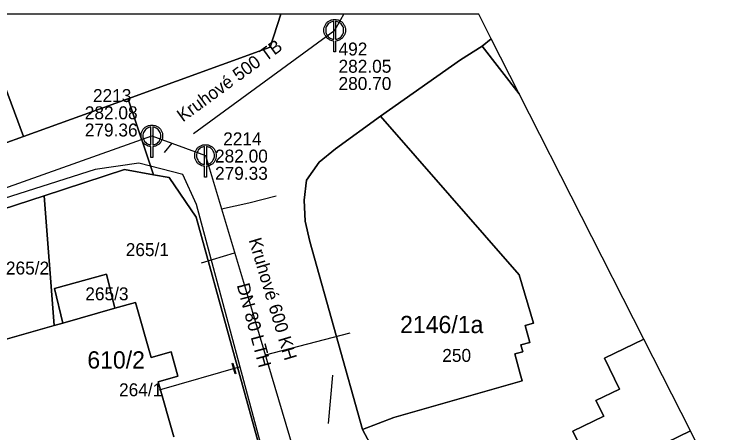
# Model space of a CAD drawing. Extents: x -571312 to -571060, y -1087128 to -1086933.
# Drawn here: x -571153.9 to -571071.4, y -1086981.5 to -1086932.9 of the extents above; entities that cross this region are included whole.
import ezdxf

# ---------------------------------------------------------------- set-up
doc = ezdxf.new("R2010")
doc.units = 0
for name, color, linetype in [('Adresní místo-text', 7, 'Continuous'), ('Armatura vodovodní', 7, 'Continuous'), ('Default', 7, 'Continuous'), ('Kanalizační přípojka', 7, 'Continuous'), ('Kanalizační stoka', 7, 'Continuous'), ('Kanalizační šachta', 7, 'Continuous'), ('Parcela-polygon', 7, 'Continuous'), ('Parcela-text', 7, 'Continuous'), ('Popis kmenové stoky', 7, 'Continuous'), ('Popis šachty', 7, 'Continuous'), ('Vodovodní přípojka', 7, 'Continuous'), ('Vodovodní řad', 7, 'Continuous'), ('Řad vodovodní popis', 7, 'Continuous')]:
    doc.layers.add(name, color=color, linetype=linetype)

msp = doc.modelspace()

# ---------------------------------------------------------------- linework, layer by layer
at = {"layer": 'Armatura vodovodní'}
msp.add_lwpolyline([(-571128.541, -1086973.395), (-571128.193, -1086974.595), (-571128.268, -1086974.617), (-571128.616, -1086973.417), (-571128.541, -1086973.395)], dxfattribs=at)
at = {"layer": 'Default'}
for points in [[(-571116.813, -1086935.988), (-571117.071, -1086935.97), (-571117.333, -1086935.824), (-571117.63, -1086935.66), (-571117.795, -1086935.363), (-571117.96, -1086935.065), (-571117.96, -1086934.74), (-571117.96, -1086934.413), (-571117.792, -1086934.113), (-571117.623, -1086933.812), (-571117.325, -1086933.651), (-571117.027, -1086933.49), (-571116.71, -1086933.49), (-571116.395, -1086933.49), (-571116.096, -1086933.651), (-571115.797, -1086933.812), (-571115.628, -1086934.113), (-571115.46, -1086934.413), (-571115.46, -1086934.74), (-571115.46, -1086935.065), (-571115.625, -1086935.363), (-571115.79, -1086935.66), (-571116.087, -1086935.824), (-571116.349, -1086935.97), (-571116.607, -1086935.988)], [(-571116.813, -1086933.702), (-571117.01, -1086933.719), (-571117.225, -1086933.834), (-571117.474, -1086933.969), (-571117.613, -1086934.219), (-571117.752, -1086934.469), (-571117.752, -1086934.74), (-571117.752, -1086935.011), (-571117.616, -1086935.258), (-571117.479, -1086935.504), (-571117.23, -1086935.641), (-571117.018, -1086935.761), (-571116.813, -1086935.775)], [(-571116.607, -1086935.775), (-571116.402, -1086935.761), (-571116.188, -1086935.641), (-571115.941, -1086935.504), (-571115.804, -1086935.258), (-571115.668, -1086935.011), (-571115.668, -1086934.74), (-571115.668, -1086934.469), (-571115.808, -1086934.219), (-571115.948, -1086933.969), (-571116.197, -1086933.834), (-571116.41, -1086933.719), (-571116.607, -1086933.702)], [(-571138.053, -1086948.248), (-571138.311, -1086948.23), (-571138.573, -1086948.084), (-571138.87, -1086947.92), (-571139.035, -1086947.623), (-571139.2, -1086947.325), (-571139.2, -1086947), (-571139.2, -1086946.673), (-571139.032, -1086946.373), (-571138.863, -1086946.072), (-571138.565, -1086945.911), (-571138.267, -1086945.75), (-571137.95, -1086945.75), (-571137.635, -1086945.75), (-571137.336, -1086945.911), (-571137.037, -1086946.072), (-571136.868, -1086946.373), (-571136.7, -1086946.673), (-571136.7, -1086947), (-571136.7, -1086947.325), (-571136.865, -1086947.623), (-571137.03, -1086947.92), (-571137.327, -1086948.084), (-571137.589, -1086948.23), (-571137.847, -1086948.248)], [(-571138.053, -1086945.962), (-571138.25, -1086945.979), (-571138.465, -1086946.094), (-571138.714, -1086946.229), (-571138.853, -1086946.479), (-571138.992, -1086946.729), (-571138.992, -1086947), (-571138.992, -1086947.271), (-571138.856, -1086947.518), (-571138.719, -1086947.764), (-571138.47, -1086947.901), (-571138.258, -1086948.021), (-571138.053, -1086948.035)], [(-571137.847, -1086948.035), (-571137.642, -1086948.021), (-571137.428, -1086947.901), (-571137.181, -1086947.764), (-571137.044, -1086947.518), (-571136.908, -1086947.271), (-571136.908, -1086947), (-571136.908, -1086946.729), (-571137.048, -1086946.479), (-571137.188, -1086946.229), (-571137.437, -1086946.094), (-571137.65, -1086945.979), (-571137.847, -1086945.962)], [(-571131.823, -1086950.528), (-571132.081, -1086950.51), (-571132.343, -1086950.364), (-571132.64, -1086950.2), (-571132.805, -1086949.903), (-571132.97, -1086949.605), (-571132.97, -1086949.28), (-571132.97, -1086948.953), (-571132.802, -1086948.653), (-571132.633, -1086948.352), (-571132.335, -1086948.191), (-571132.037, -1086948.03), (-571131.72, -1086948.03), (-571131.405, -1086948.03), (-571131.106, -1086948.191), (-571130.807, -1086948.352), (-571130.638, -1086948.653), (-571130.47, -1086948.953), (-571130.47, -1086949.28), (-571130.47, -1086949.605), (-571130.635, -1086949.903), (-571130.8, -1086950.2), (-571131.097, -1086950.364), (-571131.359, -1086950.51), (-571131.617, -1086950.528)], [(-571131.823, -1086948.242), (-571132.02, -1086948.259), (-571132.235, -1086948.374), (-571132.484, -1086948.509), (-571132.623, -1086948.759), (-571132.762, -1086949.009), (-571132.762, -1086949.28), (-571132.762, -1086949.551), (-571132.626, -1086949.798), (-571132.489, -1086950.044), (-571132.24, -1086950.181), (-571132.028, -1086950.301), (-571131.823, -1086950.315)], [(-571131.617, -1086950.315), (-571131.412, -1086950.301), (-571131.198, -1086950.181), (-571130.951, -1086950.044), (-571130.814, -1086949.798), (-571130.678, -1086949.551), (-571130.678, -1086949.28), (-571130.678, -1086949.009), (-571130.818, -1086948.759), (-571130.958, -1086948.509), (-571131.207, -1086948.374), (-571131.42, -1086948.259), (-571131.617, -1086948.242)]]:
    msp.add_open_spline(points, degree=3, dxfattribs=at)
at = {"layer": 'Kanalizační přípojka'}
for points in [[(-571136.49, -1086948.93), (-571135.602, -1086947.859)], [(-571123.49, -1086954.01), (-571126.688, -1086954.809), (-571129.856, -1086955.507)], [(-571132.17, -1086961.73), (-571128.336, -1086960.584)], [(-571114.96, -1086969.9), (-571119.871, -1086971.179), (-571124.782, -1086972.458)], [(-571116.949, -1086974.78), (-571117.47, -1086980.4)]]:
    msp.add_lwpolyline(points, dxfattribs=at)
at = {"layer": 'Kanalizační stoka'}
for p, q in [((-571116.71, -1086934.74), (-571115.638, -1086932.879)), ((-571133.109, -1086946.719), (-571116.71, -1086934.74))]:
    msp.add_line(p, q, dxfattribs=at)
for points in [[(-571180.44, -1086962.06), (-571159.195, -1086954.53), (-571137.95, -1086947)], [(-571137.95, -1086947), (-571131.72, -1086949.28)], [(-571131.72, -1086949.28), (-571125.925, -1086968.64), (-571120.13, -1086988)]]:
    msp.add_lwpolyline(points, dxfattribs=at)
at = {"layer": 'Kanalizační šachta'}
for points in [[(-571116.813, -1086935.775), (-571116.813, -1086933.702)], [(-571116.607, -1086933.702), (-571116.607, -1086935.775)], [(-571116.607, -1086935.988), (-571116.607, -1086937.24), (-571116.813, -1086937.24), (-571116.813, -1086935.988)], [(-571138.053, -1086948.035), (-571138.053, -1086945.962)], [(-571137.847, -1086945.962), (-571137.847, -1086948.035)], [(-571137.847, -1086948.248), (-571137.847, -1086949.5), (-571138.053, -1086949.5), (-571138.053, -1086948.248)], [(-571131.823, -1086950.315), (-571131.823, -1086948.242)], [(-571131.617, -1086948.242), (-571131.617, -1086950.315)], [(-571131.617, -1086950.528), (-571131.617, -1086951.78), (-571131.823, -1086951.78), (-571131.823, -1086950.528)]]:
    msp.add_lwpolyline(points, dxfattribs=at)
at = {"layer": 'Parcela-polygon'}
for p, q in [((-571122.956, -1086932.879), (-571154.996, -1086932.879)), ((-571099.973, -1086932.879), (-571122.956, -1086932.879)), ((-571098.526, -1086935.725), (-571099.973, -1086932.879)), ((-571095.268, -1086942.132), (-571098.526, -1086935.725)), ((-571080.801, -1086970.583), (-571095.268, -1086942.132)), ((-571075.377, -1086981.251), (-571080.801, -1086970.583)), ((-571071.391, -1086989.088), (-571075.377, -1086981.251))]:
    msp.add_line(p, q, dxfattribs=at)
for points in [[(-571178.531, -1086935.733), (-571177.54, -1086938.59), (-571178.01, -1086938.75), (-571176.49, -1086943.16), (-571176.01, -1086943), (-571174.12, -1086948.46), (-571168.43, -1086946.49), (-571167.94, -1086947.9), (-571162.06, -1086945.86), (-571162.55, -1086944.45), (-571157.09, -1086942.55), (-571155.22, -1086947.92), (-571152.86, -1086947.07), (-571156.82, -1086936.52), (-571158.01, -1086933.25), (-571159.84, -1086933.88), (-571159.977, -1086933.483)], [(-571122.956, -1086932.879), (-571124.19, -1086936.69), (-571140.74, -1086942.7), (-571140.64, -1086942.98), (-571137.75, -1086951.51), (-571135.94, -1086951.84), (-571132.79, -1086956.45), (-571124.52, -1086986.44), (-571125.5, -1086992.28), (-571128.52, -1086997.05), (-571130.59, -1086998.74), (-571133.51, -1087000.65), (-571144.15, -1087007.02), (-571152.8, -1087012.2), (-571165.57, -1087019.85)], [(-571159.977, -1086933.483), (-571159.84, -1086933.88), (-571158.01, -1086933.25), (-571156.82, -1086936.52), (-571152.86, -1086947.07), (-571140.74, -1086942.7), (-571124.19, -1086936.69), (-571122.956, -1086932.879)], [(-571159.39, -1087027.73), (-571150.57, -1087022.45), (-571141.52, -1087017.13), (-571133.26, -1087012.24), (-571123.41, -1087006.48), (-571114.43, -1087001.2), (-571111.37, -1086999.41), (-571110.31, -1086993.17), (-571109.12, -1086986.12), (-571112.01, -1086983.83), (-571113.46, -1086981.09), (-571119.61, -1086959.25), (-571120.15, -1086956.91), (-571120.27, -1086954.47), (-571119.98, -1086952.15), (-571118.5, -1086950.05), (-571116.6, -1086948.51), (-571111.4, -1086944.73), (-571102.09, -1086938.18), (-571099.58, -1086936.57), (-571098.526, -1086935.725)], [(-571098.526, -1086935.725), (-571099.58, -1086936.57), (-571095.268, -1086942.132)], [(-571095.268, -1086942.132), (-571099.58, -1086936.57), (-571102.09, -1086938.18), (-571111.4, -1086944.73), (-571095.29, -1086963.14), (-571093.62, -1086968.75), (-571094.58, -1086969.01), (-571094.04, -1086970.97), (-571095.08, -1086971.25), (-571094.86, -1086972.05), (-571095.79, -1086972.31), (-571095.15, -1086974.62), (-571094.93, -1086975.43), (-571109.82, -1086979.67), (-571113.46, -1086981.09), (-571112.01, -1086983.83), (-571109.12, -1086986.12), (-571105.91, -1086988), (-571101.62, -1086990.38), (-571071.391, -1086989.088)], [(-571168.71, -1086959.87), (-571150.45, -1086953.94), (-571141.12, -1086950.91), (-571137.75, -1086951.51), (-571140.64, -1086942.98), (-571140.74, -1086942.7), (-571152.86, -1086947.07), (-571155.22, -1086947.92)], [(-571124.52, -1086986.44), (-571132.79, -1086956.45), (-571135.94, -1086951.84), (-571137.75, -1086951.51), (-571141.12, -1086950.91), (-571150.45, -1086953.94), (-571149.28, -1086969.01), (-571148.29, -1086968.73), (-571149.27, -1086964.72), (-571143.22, -1086963.04), (-571142.24, -1086967), (-571139.86, -1086966.32), (-571138.03, -1086972.74), (-571135.72, -1086972.08), (-571134.94, -1086974.89), (-571137.22, -1086975.55), (-571135.4, -1086981.93)], [(-571135.4, -1086981.93), (-571137.22, -1086975.55), (-571134.94, -1086974.89), (-571135.72, -1086972.08), (-571138.03, -1086972.74), (-571139.86, -1086966.32), (-571142.24, -1086967), (-571148.29, -1086968.73), (-571149.28, -1086969.01), (-571156.67, -1086971.09)], [(-571075.377, -1086981.251), (-571086.45, -1086986.62), (-571089.06, -1086981.26), (-571085.46, -1086979.53), (-571086.37, -1086977.73), (-571083.64, -1086976.38), (-571085.38, -1086972.81), (-571080.801, -1086970.583)], [(-571080.801, -1086970.583), (-571085.38, -1086972.81), (-571083.64, -1086976.38), (-571086.37, -1086977.73), (-571085.46, -1086979.53), (-571089.06, -1086981.26), (-571086.45, -1086986.62), (-571075.377, -1086981.251)]]:
    msp.add_lwpolyline(points, dxfattribs=at)
for points in [[(-571095.08, -1086971.25), (-571094.04, -1086970.97), (-571094.58, -1086969.01), (-571093.62, -1086968.75), (-571095.29, -1086963.14), (-571111.4, -1086944.73), (-571116.6, -1086948.51), (-571118.5, -1086950.05), (-571119.98, -1086952.15), (-571120.27, -1086954.47), (-571120.15, -1086956.91), (-571119.61, -1086959.25), (-571113.46, -1086981.09), (-571109.82, -1086979.67), (-571094.93, -1086975.43), (-571095.15, -1086974.62), (-571095.79, -1086972.31), (-571094.86, -1086972.05)], [(-571168.71, -1086959.87), (-571166.79, -1086963.56), (-571161.39, -1086961.6), (-571159.84, -1086964.71), (-571158.34, -1086967.73), (-571156.67, -1086971.09), (-571149.28, -1086969.01), (-571150.45, -1086953.94)], [(-571149.27, -1086964.72), (-571148.29, -1086968.73), (-571142.24, -1086967), (-571143.22, -1086963.04)]]:
    msp.add_lwpolyline(points, close=True, dxfattribs=at)
at = {"layer": 'Vodovodní přípojka'}
msp.add_line((-571127.706, -1086973.803), (-571137.102, -1086976.532), dxfattribs=at)
at = {"layer": 'Vodovodní řad'}
msp.add_lwpolyline([(-571118.52, -1087001.2), (-571118.67, -1087000.053), (-571123.745, -1086988.554), (-571132.766, -1086954.96), (-571134.366, -1086951.47), (-571139.458, -1086950.161), (-571144.547, -1086950.9), (-571169.366, -1086958.786), (-571197.91, -1086970.492), (-571213.143, -1086976.341), (-571239.84, -1086984.572), (-571249.273, -1086987.925), (-571267.719, -1086980.097), (-571298.302, -1086956.821), (-571302.312, -1086953.213), (-571303.56, -1086950.89)], dxfattribs=at)

# ---------------------------------------------------------------- texts
at = {"layer": 'Adresní místo-text'}
for s, p in [('2146/1a', (-571109.108, -1086969.89)), ('610/2', (-571145.445, -1086974))]:
    msp.add_text(s, height=2, dxfattribs=at).set_placement(p)
at = {"layer": 'Parcela-text'}
for s, p in [('265/1', (-571140.98, -1086960.95)), ('265/2', (-571154.9, -1086963.09)), ('265/3', (-571145.68, -1086966.08)), ('250', (-571104.21, -1086973.23)), ('264/1', (-571141.76, -1086977.22))]:
    msp.add_text(s, height=1.5, dxfattribs=at).set_placement(p)
at = {"layer": 'Popis kmenové stoky'}
for s, rotation, p in [('Kruhové 500 TB', 36.14705, (-571134.346, -1086945.452)), ('Kruhové 600 KH', 286.66394, (-571126.717, -1086959.084))]:
    msp.add_text(s, height=1.5, rotation=rotation, dxfattribs=at).set_placement(p)
at = {"layer": 'Popis šachty'}
for s, p in [('492', (-571116.262, -1086937.669)), ('282.05', (-571116.262, -1086939.669)), ('280.70', (-571116.262, -1086941.669)), ('2213', (-571144.79, -1086943.069)), ('282.08', (-571145.739, -1086945.069)), ('279.36', (-571145.739, -1086947.069)), ('2214', (-571129.661, -1086948.094)), ('282.00', (-571130.61, -1086950.094)), ('279.33', (-571130.61, -1086952.094))]:
    msp.add_text(s, height=1.5, dxfattribs=at).set_placement(p)
at = {"layer": 'Řad vodovodní popis'}
msp.add_text('DN 80 LTH', height=1.5, rotation=285.03103, dxfattribs=at).set_placement((-571128.097, -1086964.319))

doc.saveas('drawing.dxf')
